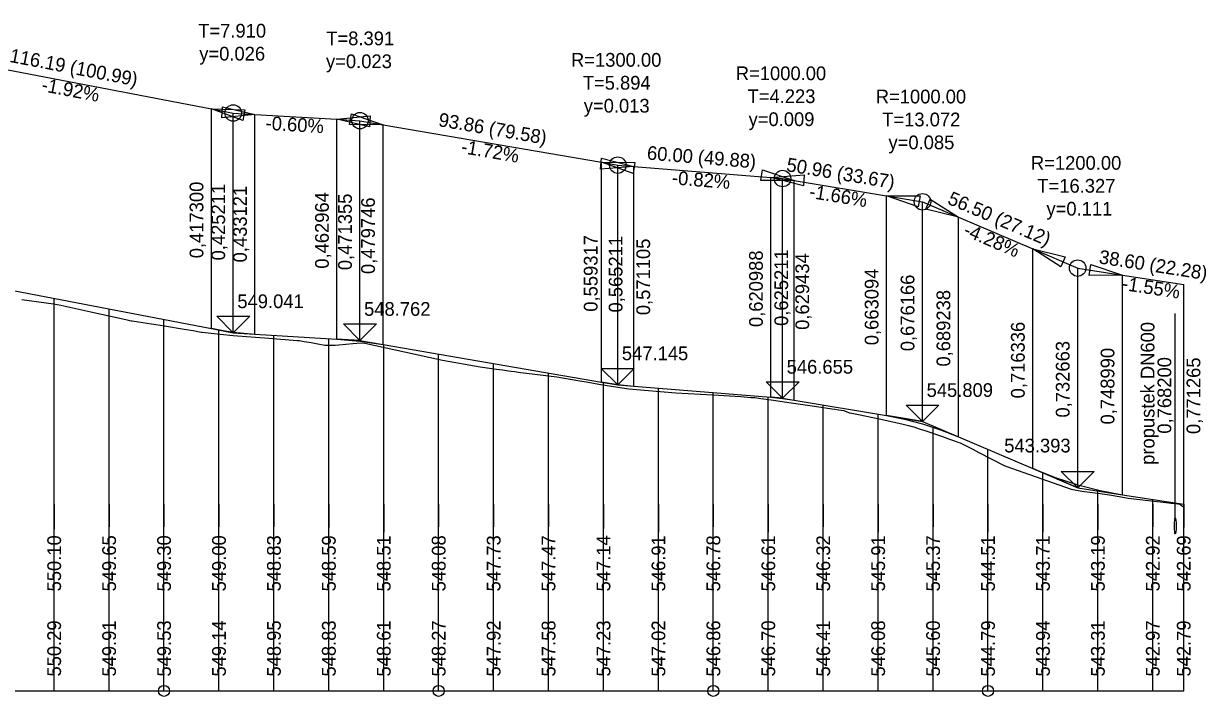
# Model space of a CAD drawing. Extents: x -603528 to -602138, y -1111983 to -1111218.
# Drawn here: x -603007.2 to -602576.6, y -1111709.4 to -1111464.4 of the extents above; entities that cross this region are included whole.
import ezdxf

# ---------------------------------------------------------------- set-up
doc = ezdxf.new("R2010")
doc.units = 0
for name, color, linetype in [('_křivky z hran', 7, 'Continuous'), ('C3D_PP-Navrh', 7, 'Continuous'), ('C3D_PP-Popisek', 7, 'Continuous'), ('C3D_PP-Teren', 7, 'Continuous'), ('C3D_ZPP', 7, 'Continuous'), ('C3D_ZPP-Prouzky', 7, 'Continuous'), ('Default', 7, 'Continuous')]:
    doc.layers.add(name, color=color, linetype=linetype)

# ---------------------------------------------------------------- blocks, each defined once
blk = doc.blocks.new('hekto-krouzek')
at = {"layer": 'Default'}
blk.add_circle((0, 0), 1.5, dxfattribs=at)
blk = doc.blocks.new('PP-sipka')
at = {"layer": 'Default'}
for p, q in [((0, 0), (-4, 4)), ((-4, 4), (4, 4)), ((4, 4), (0, 0))]:
    blk.add_line(p, q, dxfattribs=at)
blk = doc.blocks.new('AeccTickCircle')
at = {"layer": 'Default'}
blk.add_circle((0, 0), 0.5, dxfattribs=at)
blk = doc.blocks.new('AeccArwClosedFilled')
at = {"layer": 'Default'}
blk.add_lwpolyline([(0.18, 0.03), (0.18, -0.03), (0, 0)], close=True, dxfattribs=at)

msp = doc.modelspace()

# ---------------------------------------------------------------- linework, layer by layer
at = {"layer": 'C3D_PP-Navrh'}
for p, q in [((-603039.75, -1111556.03), (-602938.77, -1111575.44)), ((-602938.77, -1111575.44), (-602930.86, -1111576.96)), ((-602930.86, -1111576.96), (-602922.95, -1111577.44)), ((-602922.95, -1111577.44), (-602893.11, -1111579.25)), ((-602893.11, -1111579.25), (-602884.72, -1111579.75)), ((-602884.72, -1111579.75), (-602876.33, -1111581.2)), ((-602876.33, -1111581.2), (-602796.76, -1111594.91)), ((-602796.76, -1111594.91), (-602790.86, -1111595.93)), ((-602790.86, -1111595.93), (-602784.97, -1111596.41)), ((-602784.97, -1111596.41), (-602735.09, -1111600.48)), ((-602735.09, -1111600.48), (-602730.86, -1111600.82)), ((-602730.86, -1111600.82), (-602726.64, -1111601.53)), ((-602726.64, -1111601.53), (-602692.98, -1111607.12)), ((-602692.98, -1111607.12), (-602679.91, -1111609.29)), ((-602679.91, -1111609.29), (-602666.84, -1111614.88)), ((-602666.84, -1111614.88), (-602639.74, -1111626.46)), ((-602639.74, -1111626.46), (-602623.41, -1111633.44)), ((-602623.41, -1111633.44), (-602607.08, -1111635.98)), ((-602607.08, -1111635.98), (-602584.81, -1111639.44))]:
    msp.add_line(p, q, dxfattribs=at)
for points in [[(-602938.77, -1111575.44), (-602930.86, -1111576.7), (-602922.95, -1111577.44)], [(-602893.11, -1111579.25), (-602884.72, -1111579.99), (-602876.33, -1111581.2)], [(-602796.76, -1111594.91), (-602790.86, -1111595.79), (-602784.97, -1111596.41)], [(-602735.09, -1111600.48), (-602730.86, -1111600.91), (-602726.64, -1111601.53)], [(-602692.98, -1111607.12), (-602686.44, -1111608.42), (-602679.91, -1111610.14), (-602673.37, -1111612.3), (-602666.84, -1111614.88)], [(-602639.74, -1111626.46), (-602631.57, -1111629.67), (-602623.41, -1111632.33), (-602615.25, -1111634.43), (-602607.08, -1111635.98)]]:
    msp.add_lwpolyline(points, dxfattribs=at)
at = {"layer": 'C3D_PP-Popisek'}
for p, q in [((-603039.75, -1111476.03), (-602938.77, -1111495.44)), ((-602938.77, -1111575.44), (-602938.77, -1111495.44)), ((-602938.77, -1111575.44), (-602938.77, -1111495.44)), ((-602938.77, -1111495.44), (-602930.86, -1111496.96)), ((-602930.86, -1111576.96), (-602930.86, -1111496.96)), ((-602930.86, -1111496.96), (-602922.95, -1111497.44)), ((-602922.95, -1111577.44), (-602922.95, -1111497.44)), ((-602922.95, -1111497.44), (-602893.11, -1111499.25)), ((-602922.95, -1111577.44), (-602922.95, -1111497.44)), ((-602893.11, -1111579.25), (-602893.11, -1111499.25)), ((-602893.11, -1111579.25), (-602893.11, -1111499.25)), ((-602893.11, -1111499.25), (-602884.72, -1111499.75)), ((-602884.72, -1111579.75), (-602884.72, -1111499.75)), ((-602884.72, -1111499.75), (-602876.33, -1111501.2)), ((-602876.33, -1111581.2), (-602876.33, -1111501.2)), ((-602876.33, -1111501.2), (-602796.76, -1111514.91)), ((-602876.33, -1111581.2), (-602876.33, -1111501.2)), ((-602796.76, -1111594.91), (-602796.76, -1111514.91)), ((-602796.76, -1111594.91), (-602796.76, -1111514.91)), ((-602796.76, -1111514.91), (-602790.86, -1111515.93)), ((-602790.86, -1111595.93), (-602790.86, -1111515.93)), ((-602790.86, -1111515.93), (-602784.97, -1111516.41)), ((-602784.97, -1111596.41), (-602784.97, -1111516.41)), ((-602784.97, -1111516.41), (-602735.09, -1111520.48)), ((-602784.97, -1111596.41), (-602784.97, -1111516.41)), ((-602735.09, -1111600.48), (-602735.09, -1111520.48)), ((-602735.09, -1111600.48), (-602735.09, -1111520.48)), ((-602735.09, -1111520.48), (-602730.86, -1111520.82)), ((-602730.86, -1111600.82), (-602730.86, -1111520.82)), ((-602730.86, -1111520.82), (-602726.64, -1111521.53)), ((-602726.64, -1111601.53), (-602726.64, -1111521.53)), ((-602726.64, -1111521.53), (-602692.98, -1111527.12)), ((-602726.64, -1111601.53), (-602726.64, -1111521.53)), ((-602692.98, -1111607.12), (-602692.98, -1111527.12)), ((-602692.98, -1111607.12), (-602692.98, -1111527.12)), ((-602692.98, -1111527.12), (-602679.91, -1111529.29)), ((-602679.91, -1111609.29), (-602679.91, -1111529.29)), ((-602679.91, -1111529.29), (-602666.84, -1111534.88)), ((-602666.84, -1111614.88), (-602666.84, -1111534.88)), ((-602666.84, -1111534.88), (-602639.74, -1111546.46)), ((-602666.84, -1111614.88), (-602666.84, -1111534.88)), ((-602639.74, -1111626.46), (-602639.74, -1111546.46)), ((-602639.74, -1111626.46), (-602639.74, -1111546.46)), ((-602639.74, -1111546.46), (-602623.41, -1111553.44)), ((-602623.41, -1111633.44), (-602623.41, -1111553.44)), ((-602623.41, -1111553.44), (-602607.08, -1111555.98)), ((-602607.08, -1111635.98), (-602607.08, -1111555.98)), ((-602607.08, -1111555.98), (-602584.81, -1111559.44)), ((-602607.08, -1111635.98), (-602607.08, -1111555.98)), ((-602584.81, -1111639.44), (-602584.81, -1111559.44)), ((-602587.87, -1111644.35), (-602587.87, -1111569.9)), ((-602930.86, -1111576.96), (-602938.77, -1111575.44)), ((-602930.86, -1111576.96), (-602922.95, -1111577.44)), ((-602884.72, -1111579.75), (-602893.11, -1111579.25)), ((-602884.72, -1111579.75), (-602876.33, -1111581.2)), ((-602790.86, -1111595.93), (-602796.76, -1111594.91)), ((-602790.86, -1111595.93), (-602784.97, -1111596.41)), ((-602730.86, -1111600.82), (-602735.09, -1111600.48)), ((-602730.86, -1111600.82), (-602726.64, -1111601.53)), ((-602679.91, -1111609.29), (-602692.98, -1111607.12)), ((-602679.91, -1111609.29), (-602666.84, -1111614.88)), ((-602623.41, -1111633.44), (-602639.74, -1111626.46)), ((-602623.41, -1111633.44), (-602607.08, -1111635.98))]:
    msp.add_line(p, q, dxfattribs=at)
msp.add_ellipse((-602587.87, -1111647.35), major_axis=(0, -3), ratio=0.1, dxfattribs=at)
at = {"layer": 'C3D_PP-Teren'}
for p, q in [((-603007.86, -1111564.84), (-602998.92, -1111566.03)), ((-602998.92, -1111566.03), (-602996.28, -1111566.38)), ((-602996.28, -1111566.38), (-602996.28, -1111566.38)), ((-602996.28, -1111566.38), (-602993.64, -1111566.96)), ((-602993.64, -1111566.96), (-602982.72, -1111569.39)), ((-602982.72, -1111569.39), (-602969.98, -1111572.18)), ((-602969.98, -1111572.18), (-602967.97, -1111572.62)), ((-602967.97, -1111572.62), (-602967.64, -1111572.67)), ((-602967.64, -1111572.67), (-602965.3, -1111573.02)), ((-602965.3, -1111573.02), (-602955.9, -1111574.42)), ((-602955.9, -1111574.42), (-602948.74, -1111575.64)), ((-602948.74, -1111575.64), (-602945.46, -1111576.2)), ((-602945.46, -1111576.2), (-602942.58, -1111576.7)), ((-602942.58, -1111576.7), (-602942.18, -1111576.74)), ((-602942.18, -1111576.74), (-602938.9, -1111577.09)), ((-602938.9, -1111577.09), (-602935.62, -1111577.45)), ((-602935.62, -1111577.45), (-602930.84, -1111577.98)), ((-602930.84, -1111577.98), (-602917.86, -1111578.98)), ((-602917.86, -1111578.98), (-602907.58, -1111579.79)), ((-602907.58, -1111579.79), (-602906.87, -1111579.84)), ((-602906.87, -1111579.84), (-602905.06, -1111580.13)), ((-602905.06, -1111580.13), (-602902.53, -1111580.55)), ((-602902.53, -1111580.55), (-602900, -1111581)), ((-602900, -1111581), (-602897.54, -1111581.46)), ((-602892.42, -1111581.36), (-602889.9, -1111581.15)), ((-602889.9, -1111581.15), (-602887.37, -1111580.94)), ((-602887.37, -1111580.94), (-602884.3, -1111580.68)), ((-602884.3, -1111580.68), (-602882.96, -1111580.82)), ((-602882.96, -1111580.82), (-602868.56, -1111583.95)), ((-602897.54, -1111581.46), (-602897.48, -1111581.46)), ((-602897.48, -1111581.46), (-602894.95, -1111581.46)), ((-602894.95, -1111581.46), (-602893.8, -1111581.48)), ((-602893.8, -1111581.48), (-602892.42, -1111581.36)), ((-602868.56, -1111583.95), (-602854.63, -1111586.92)), ((-602854.63, -1111586.92), (-602840.93, -1111589.37)), ((-602840.93, -1111589.37), (-602835.04, -1111590.22)), ((-602835.04, -1111590.22), (-602832.86, -1111590.53)), ((-602832.86, -1111590.53), (-602830.67, -1111590.83)), ((-602830.67, -1111590.83), (-602829.65, -1111590.97)), ((-602829.65, -1111590.97), (-602828.49, -1111591.12)), ((-602828.49, -1111591.12), (-602826.3, -1111591.4)), ((-602826.3, -1111591.4), (-602824.12, -1111591.66)), ((-602824.12, -1111591.66), (-602813.06, -1111592.99)), ((-602813.06, -1111592.99), (-602805.42, -1111594.35)), ((-602805.42, -1111594.35), (-602801.6, -1111595.02)), ((-602801.6, -1111595.02), (-602799.69, -1111595.33)), ((-602799.69, -1111595.33), (-602797.78, -1111595.66)), ((-602797.78, -1111595.66), (-602793.96, -1111596.27)), ((-602793.96, -1111596.27), (-602786.82, -1111597.39)), ((-602786.82, -1111597.39), (-602769.74, -1111598.87)), ((-602769.74, -1111598.87), (-602756.24, -1111599.57)), ((-602756.24, -1111599.57), (-602746.1, -1111600.24)), ((-602746.1, -1111600.24), (-602742.42, -1111600.49)), ((-602742.42, -1111600.49), (-602740.9, -1111600.59)), ((-602740.9, -1111600.59), (-602738.74, -1111600.89)), ((-602738.74, -1111600.89), (-602735.06, -1111601.42)), ((-602735.06, -1111601.42), (-602727.69, -1111602.47)), ((-602727.69, -1111602.47), (-602720.09, -1111603.57)), ((-602720.09, -1111603.57), (-602717.69, -1111603.92)), ((-602717.69, -1111603.92), (-602715.28, -1111604.27)), ((-602715.28, -1111604.27), (-602712.88, -1111604.63)), ((-602712.88, -1111604.63), (-602711.8, -1111604.8)), ((-602711.8, -1111604.8), (-602710.48, -1111605.01)), ((-602710.48, -1111605.01), (-602708.54, -1111605.32)), ((-602708.54, -1111605.32), (-602708.07, -1111605.49)), ((-602708.07, -1111605.49), (-602706.47, -1111606.08)), ((-602706.47, -1111606.08), (-602705.67, -1111606.24)), ((-602705.67, -1111606.24), (-602703.26, -1111606.74)), ((-602703.26, -1111606.74), (-602695.08, -1111608.45)), ((-602695.08, -1111608.45), (-602686.97, -1111610.3)), ((-602686.97, -1111610.3), (-602685, -1111610.76)), ((-602685, -1111610.76), (-602683.72, -1111611.06)), ((-602683.72, -1111611.06), (-602683.04, -1111611.29)), ((-602683.04, -1111611.29), (-602681.07, -1111611.94)), ((-602681.07, -1111611.94), (-602679.1, -1111612.61)), ((-602679.1, -1111612.61), (-602672.65, -1111614.81)), ((-602672.65, -1111614.81), (-602670.44, -1111615.57)), ((-602670.44, -1111615.57), (-602668.22, -1111616.35)), ((-602668.22, -1111616.35), (-602667, -1111616.78)), ((-602667, -1111616.78), (-602666.2, -1111617.04)), ((-602666.2, -1111617.04), (-602666, -1111617.14)), ((-602666, -1111617.14), (-602665.5, -1111617.39)), ((-602665.5, -1111617.39), (-602663.79, -1111618.24)), ((-602663.79, -1111618.24), (-602661.57, -1111619.37)), ((-602661.57, -1111619.37), (-602659.35, -1111620.53)), ((-602659.35, -1111620.53), (-602650.41, -1111625.24)), ((-602650.41, -1111625.24), (-602649.51, -1111625.55)), ((-602649.51, -1111625.55), (-602625.82, -1111633.9)), ((-602625.82, -1111633.9), (-602625.75, -1111633.91)), ((-602625.75, -1111633.91), (-602623.82, -1111634.27)), ((-602623.82, -1111634.27), (-602621.9, -1111634.6)), ((-602621.9, -1111634.6), (-602619.97, -1111634.91)), ((-602619.97, -1111634.91), (-602618.04, -1111635.19)), ((-602618.04, -1111635.19), (-602616.11, -1111635.44)), ((-602616.11, -1111635.44), (-602611.79, -1111635.98)), ((-602611.79, -1111635.98), (-602608.25, -1111636.65)), ((-602608.25, -1111636.65), (-602605.01, -1111637.15)), ((-602605.01, -1111637.15), (-602590.18, -1111638.91)), ((-602590.18, -1111638.91), (-602589.52, -1111638.99)), ((-602589.52, -1111638.99), (-602588.86, -1111639.06)), ((-602588.86, -1111639.06), (-602588.21, -1111639.13)), ((-602588.21, -1111639.13), (-602587.55, -1111639.19)), ((-602587.55, -1111639.19), (-602586.89, -1111639.25)), ((-602586.89, -1111639.25), (-602586.38, -1111639.28)), ((-602586.38, -1111639.28), (-602586.24, -1111639.39)), ((-602586.24, -1111639.39), (-602585.58, -1111639.88)), ((-602585.58, -1111639.88), (-602584.92, -1111640.36)), ((-602584.92, -1111640.36), (-602584.81, -1111640.44))]:
    msp.add_line(p, q, dxfattribs=at)
at = {"layer": 'C3D_ZPP'}
for p, q in [((-602996.07, -1111707.38), (-602996.07, -1111564.43)), ((-602976.07, -1111707.38), (-602976.07, -1111568.27)), ((-602956.07, -1111707.38), (-602956.07, -1111572.12)), ((-602936.07, -1111707.38), (-602936.07, -1111575.87)), ((-602916.07, -1111707.38), (-602916.07, -1111577.86)), ((-602896.07, -1111707.38), (-602896.07, -1111579.07)), ((-602876.07, -1111707.38), (-602876.07, -1111581.24)), ((-602856.07, -1111707.38), (-602856.07, -1111584.69)), ((-602836.07, -1111707.38), (-602836.07, -1111588.14)), ((-602816.07, -1111707.38), (-602816.07, -1111591.58)), ((-602796.07, -1111707.38), (-602796.07, -1111595.01)), ((-602776.07, -1111707.38), (-602776.07, -1111597.13)), ((-602756.07, -1111707.38), (-602756.07, -1111598.77)), ((-602736.07, -1111707.38), (-602736.07, -1111600.4)), ((-602716.07, -1111707.38), (-602716.07, -1111603.28)), ((-602696.07, -1111707.38), (-602696.07, -1111606.6)), ((-602676.07, -1111707.38), (-602676.07, -1111611.41)), ((-602656.07, -1111707.38), (-602656.07, -1111619.48)), ((-602636.07, -1111707.38), (-602636.07, -1111627.9)), ((-602616.07, -1111707.38), (-602616.07, -1111634.22)), ((-602596.07, -1111707.38), (-602596.07, -1111637.69)), ((-602584.81, -1111707.38), (-602584.81, -1111639.44)), ((-603356.07, -1111707.38), (-602584.81, -1111707.38))]:
    msp.add_line(p, q, dxfattribs=at)
at = {"layer": 'C3D_ZPP-Prouzky'}
for p, q in [((-602996.07, -1111639.42), (-602996.07, -1111648.49)), ((-602976.07, -1111639.42), (-602976.07, -1111647.63)), ((-602956.07, -1111639.42), (-602956.07, -1111647.63)), ((-602936.07, -1111639.42), (-602936.07, -1111647.63)), ((-602916.07, -1111639.42), (-602916.07, -1111647.63)), ((-602896.07, -1111639.42), (-602896.07, -1111647.84)), ((-602876.07, -1111639.42), (-602876.07, -1111649.56)), ((-602856.07, -1111639.42), (-602856.07, -1111647.63)), ((-602836.07, -1111639.42), (-602836.07, -1111647.63)), ((-602816.07, -1111639.42), (-602816.07, -1111647.63)), ((-602796.07, -1111639.42), (-602796.07, -1111648.27)), ((-602776.07, -1111639.42), (-602776.07, -1111649.56)), ((-602756.07, -1111639.42), (-602756.07, -1111647.63)), ((-602736.07, -1111639.42), (-602736.07, -1111649.56)), ((-602716.07, -1111639.42), (-602716.07, -1111647.63)), ((-602696.07, -1111639.42), (-602696.07, -1111649.56)), ((-602676.07, -1111639.42), (-602676.07, -1111647.63)), ((-602656.07, -1111639.42), (-602656.07, -1111649.56)), ((-602636.07, -1111639.42), (-602636.07, -1111649.56)), ((-602616.07, -1111639.42), (-602616.07, -1111648.7)), ((-602596.07, -1111639.42), (-602596.07, -1111647.63)), ((-602584.81, -1111639.42), (-602584.81, -1111647.84)), ((-602996.07, -1111677.42), (-602996.07, -1111672.42)), ((-602976.07, -1111677.42), (-602976.07, -1111672.42)), ((-602956.07, -1111677.42), (-602956.07, -1111672.42)), ((-602936.07, -1111677.42), (-602936.07, -1111672.42)), ((-602916.07, -1111677.42), (-602916.07, -1111672.42)), ((-602896.07, -1111677.42), (-602896.07, -1111672.42)), ((-602876.07, -1111677.42), (-602876.07, -1111672.42)), ((-602856.07, -1111677.42), (-602856.07, -1111672.42)), ((-602836.07, -1111677.42), (-602836.07, -1111672.42)), ((-602816.07, -1111677.42), (-602816.07, -1111672.42)), ((-602796.07, -1111677.42), (-602796.07, -1111672.42)), ((-602776.07, -1111677.42), (-602776.07, -1111672.42)), ((-602756.07, -1111677.42), (-602756.07, -1111672.42)), ((-602736.07, -1111677.42), (-602736.07, -1111672.42)), ((-602716.07, -1111677.42), (-602716.07, -1111672.42)), ((-602696.07, -1111677.42), (-602696.07, -1111672.42)), ((-602676.07, -1111677.42), (-602676.07, -1111672.42)), ((-602656.07, -1111677.42), (-602656.07, -1111672.42)), ((-602636.07, -1111677.42), (-602636.07, -1111672.42)), ((-602616.07, -1111677.42), (-602616.07, -1111672.42)), ((-602596.07, -1111677.42), (-602596.07, -1111672.42)), ((-602584.81, -1111677.42), (-602584.81, -1111672.42))]:
    msp.add_line(p, q, dxfattribs=at)

# ---------------------------------------------------------------- block references
at = {"layer": '_křivky z hran'}
for p, xscale, yscale, rotation in [((-602938.77, -1111495.44), 66.66666666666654, 66.66666666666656, -10.883673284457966), ((-602922.95, -1111497.44), 66.66666666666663, 66.66666666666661, 176.54152380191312), ((-602893.11, -1111499.25), 66.66666666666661, 66.66666666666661, -3.4584761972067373), ((-602876.33, -1111501.2), 66.66666666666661, 66.66666666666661, 170.22320762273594), ((-602796.76, -1111514.91), 66.66666666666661, 66.66666666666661, -9.776792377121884), ((-602784.97, -1111516.41), 66.66666666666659, 66.66666666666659, 175.3327193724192), ((-602726.64, -1111521.53), 66.66666666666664, 66.66666666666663, 170.56928101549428), ((-602735.09, -1111520.48), 66.66666666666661, 66.66666666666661, -4.667280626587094), ((-602692.98, -1111527.12), 66.6666666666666, 66.66666666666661, -9.430718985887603), ((-602666.84, -1111534.88), 66.66666666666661, 66.66666666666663, 156.85133402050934), ((-602639.74, -1111546.46), 66.66666666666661, 66.66666666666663, -23.14866597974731), ((-602607.08, -1111555.98), 66.66666666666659, 66.6666666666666, 171.16556980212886)]:
    msp.add_blockref('AeccArwClosedFilled', p, dxfattribs=dict(at, xscale=xscale, yscale=yscale, rotation=rotation))
for name, p, xscale, yscale in [('PP-sipka', (-602930.86, -1111576.96), 1.5, 1.5), ('PP-sipka', (-602884.72, -1111579.75), 1.5, 1.5), ('PP-sipka', (-602790.86, -1111595.93), 1.5, 1.5), ('PP-sipka', (-602730.86, -1111600.82), 1.5, 1.5), ('PP-sipka', (-602679.91, -1111609.29), 1.5, 1.5), ('PP-sipka', (-602623.41, -1111633.44), 1.5, 1.5), ('hekto-krouzek', (-602956.07, -1111707.38), 1.3333333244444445, 1.3333333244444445), ('hekto-krouzek', (-602856.07, -1111707.38), 1.3333333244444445, 1.3333333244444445), ('hekto-krouzek', (-602756.07, -1111707.38), 1.3333333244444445, 1.3333333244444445), ('hekto-krouzek', (-602656.07, -1111707.38), 1.3333333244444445, 1.3333333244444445)]:
    msp.add_blockref(name, p, dxfattribs=dict(at, xscale=xscale, yscale=yscale))
at = {"layer": 'C3D_PP-Popisek', "xscale": 5.9999998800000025, "yscale": 5.9999998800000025, "rotation": 89.99999999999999}
for p in [(-602930.86, -1111496.96), (-602884.72, -1111499.75), (-602790.86, -1111515.93), (-602730.86, -1111520.82), (-602679.91, -1111529.29), (-602623.41, -1111553.44)]:
    msp.add_blockref('AeccTickCircle', p, dxfattribs=at)

# ---------------------------------------------------------------- texts
at = {"layer": 'C3D_PP-Popisek'}
for s, rotation, p in [('T=7.910', 360, (-602943.61, -1111469.48)), ('T=8.391', 360, (-602896.99, -1111472.27)), ('y=0.026', 360, (-602943.23, -1111477.84)), ('116.19 (100.99)', 349.1163, (-603012.54, -1111478.32)), ('y=0.023', 360, (-602897.08, -1111480.62)), ('R=1300.00', 360, (-602807.88, -1111480.09)), ('R=1000.00', 360, (-602747.88, -1111484.99)), ('-1.92%', 349.1163, (-603000.92, -1111488.95)), ('T=5.894', 360, (-602803.6, -1111488.44)), ('T=4.223', 360, (-602743.61, -1111493.34)), ('R=1000.00', 360, (-602696.92, -1111493.45)), ('y=0.013', 360, (-602803.23, -1111496.8)), ('-0.60%', 356.5415, (-602919.18, -1111503.04)), ('93.86 (79.58)', 350.2232, (-602856.39, -1111501.7)), ('y=0.009', 360, (-602743.23, -1111501.7)), ('T=13.072', 360, (-602694.57, -1111501.81)), ('-1.72%', 350.2232, (-602848.14, -1111511.5)), ('y=0.085', 360, (-602692.29, -1111510.16)), ('60.00 (49.88)', 355.3327, (-602780.37, -1111513.89)), ('50.96 (33.67)', 350.5693, (-602729.7, -1111518.09)), ('R=1200.00', 360, (-602640.43, -1111517.61)), ('-0.82%', 355.3327, (-602771.27, -1111522.91)), ('T=16.327', 360, (-602638.1, -1111525.96)), ('0,417300', 90, (-602941.73, -1111549.84)), ('0,425211', 90, (-602933.82, -1111550.63)), ('0,433121', 90, (-602925.9, -1111551.36)), ('-1.66%', 350.5693, (-602721.39, -1111527.83)), ('0,462964', 90, (-602896.06, -1111553.64)), ('0,471355', 90, (-602887.67, -1111554.18)), ('0,479746', 90, (-602879.28, -1111555.6)), ('56.50 (27.12)', 336.8513, (-602671.13, -1111529.9)), ('y=0.111', 360, (-602634.77, -1111534.31)), ('0,559317', 90, (-602798.21, -1111569.31)), ('0,565211', 90, (-602789.14, -1111569.59)), ('-4.28%', 336.8513, (-602665.37, -1111541.34)), ('0,571105', 90, (-602779.08, -1111570.57)), ('38.60 (22.28)', 351.1656, (-602615.9, -1111551.69)), ('0,620988', 90, (-602738.04, -1111574.89)), ('0,625211', 90, (-602728.84, -1111574.48)), ('0,629434', 90, (-602721.18, -1111575.92)), ('0,663094', 90, (-602695.93, -1111581.51)), ('0,676166', 90, (-602682.86, -1111583.69)), ('-1.55%', 351.1656, (-602607.49, -1111561.34)), ('549.041', 360, (-602929.36, -1111568.01)), ('0,689238', 90, (-602669.79, -1111589.28)), ('548.762', 360, (-602883.22, -1111570.8)), ('0,716336', 90, (-602642.69, -1111600.87)), ('propustek DN600', 90, (-602595.46, -1111625.07)), ('0,732663', 90, (-602626.36, -1111607.85)), ('547.145', 360, (-602789.36, -1111586.97)), ('0,748990', 90, (-602610.04, -1111610.37)), ('546.655', 360, (-602729.36, -1111591.87)), ('0,768200', 90, (-602589.33, -1111613.72)), ('0,771265', 90, (-602578.75, -1111613.86)), ('545.809', 360, (-602678.41, -1111600.34)), ('543.393', 360, (-602650.15, -1111620.56))]:
    msp.add_text(s, height=5, rotation=rotation, dxfattribs=at).set_placement(p)
at = {"layer": 'C3D_ZPP-Prouzky'}
for s, p in [('550.10', (-602993.55, -1111671.17)), ('549.65', (-602973.55, -1111671.17)), ('549.30', (-602953.55, -1111671.17)), ('549.00', (-602933.55, -1111671.17)), ('548.83', (-602913.55, -1111671.17)), ('548.59', (-602893.55, -1111671.17)), ('548.51', (-602873.55, -1111671.17)), ('548.08', (-602853.55, -1111671.17)), ('547.73', (-602833.55, -1111671.17)), ('547.47', (-602813.57, -1111671.17)), ('547.14', (-602793.55, -1111671.17)), ('546.91', (-602773.55, -1111671.17)), ('546.78', (-602753.55, -1111671.17)), ('546.61', (-602733.55, -1111671.17)), ('546.32', (-602713.55, -1111671.17)), ('545.91', (-602693.55, -1111671.17)), ('545.37', (-602673.55, -1111671.17)), ('544.51', (-602653.55, -1111671.17)), ('543.71', (-602633.55, -1111671.17)), ('543.19', (-602613.55, -1111671.17)), ('542.92', (-602593.55, -1111671.17)), ('542.69', (-602582.29, -1111671.17)), ('550.29', (-602993.55, -1111702.17)), ('549.91', (-602973.55, -1111702.17)), ('549.53', (-602953.55, -1111702.17)), ('549.14', (-602933.55, -1111702.17)), ('548.95', (-602913.55, -1111702.17)), ('548.83', (-602893.55, -1111702.17)), ('548.61', (-602873.55, -1111702.17)), ('548.27', (-602853.55, -1111702.17)), ('547.92', (-602833.55, -1111702.17)), ('547.58', (-602813.55, -1111702.17)), ('547.23', (-602793.55, -1111702.17)), ('547.02', (-602773.55, -1111702.17)), ('546.86', (-602753.55, -1111702.17)), ('546.70', (-602733.55, -1111702.17)), ('546.41', (-602713.55, -1111702.17)), ('546.08', (-602693.55, -1111702.17)), ('545.60', (-602673.55, -1111702.17)), ('544.79', (-602653.55, -1111702.17)), ('543.94', (-602633.55, -1111702.17)), ('543.31', (-602613.55, -1111702.17)), ('542.97', (-602593.55, -1111702.17)), ('542.79', (-602582.29, -1111702.17))]:
    msp.add_text(s, height=5, rotation=90, dxfattribs=at).set_placement(p)

doc.saveas('drawing.dxf')
